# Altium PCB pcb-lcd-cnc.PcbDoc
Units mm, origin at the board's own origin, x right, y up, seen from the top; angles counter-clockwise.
Board outline 96.9 x 63.14 mm, 2 copper layers (Top Layer, Bottom Layer); 22 components, 40 nets, 120 pads, 47 vias.
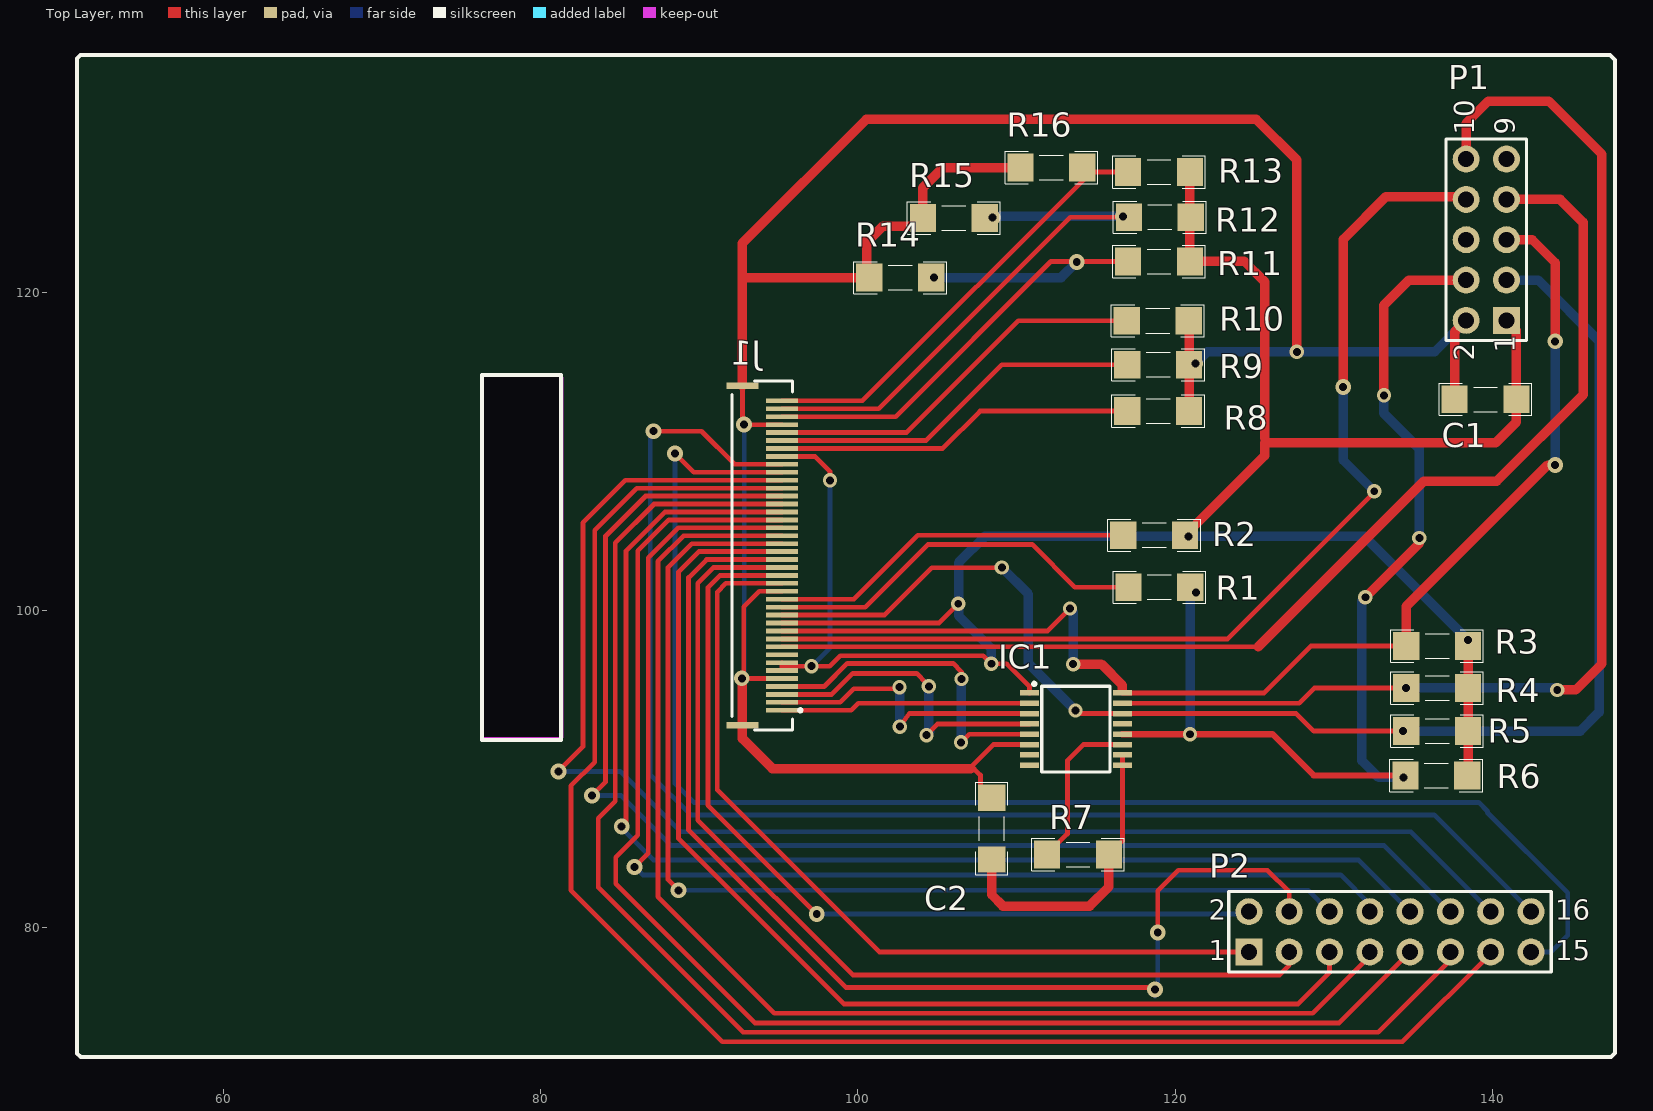
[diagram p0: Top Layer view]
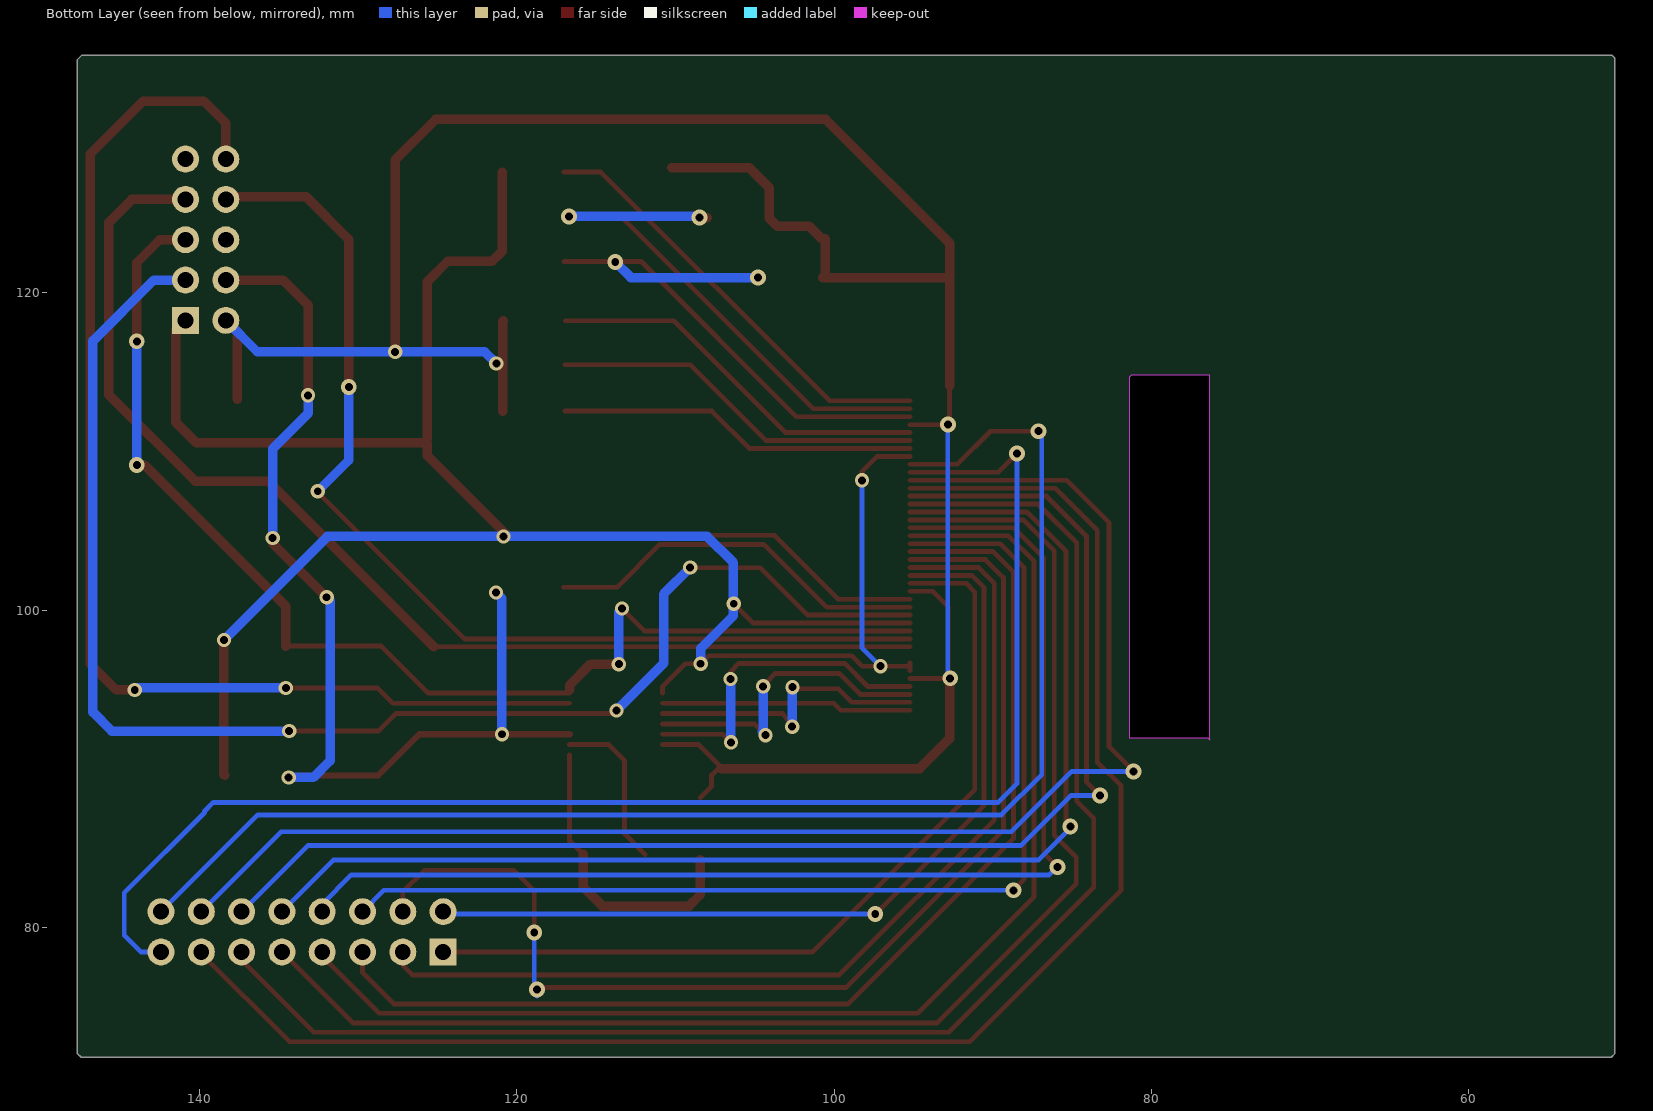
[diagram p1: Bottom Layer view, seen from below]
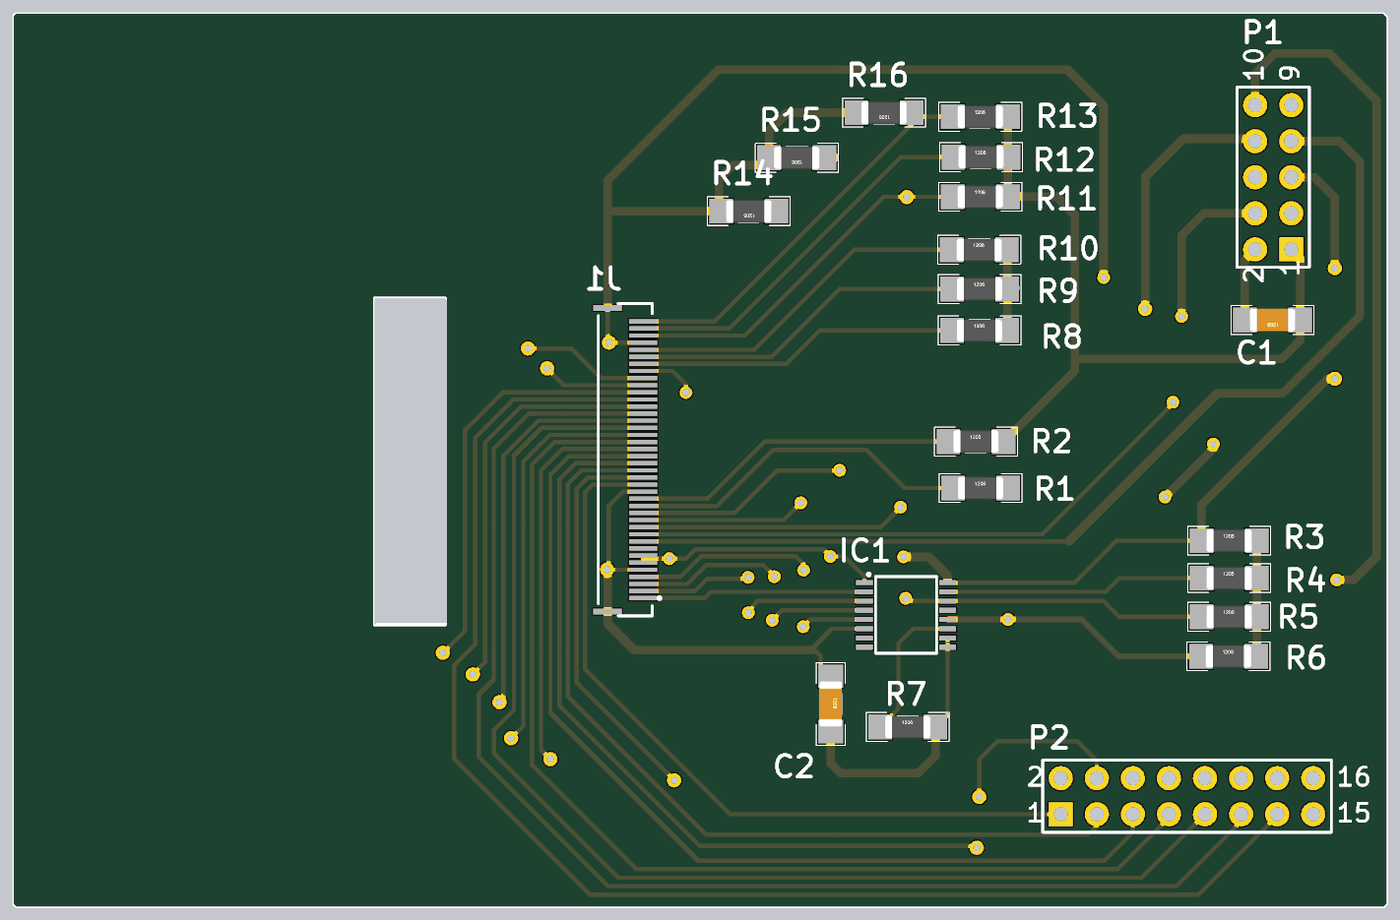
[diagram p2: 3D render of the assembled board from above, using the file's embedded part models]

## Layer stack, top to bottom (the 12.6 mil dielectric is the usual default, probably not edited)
Top Solder: solder mask 0.0102, Solder Resist, Dk 3.5
Top Layer: signal copper 0.0356
Dielectric 1: dielectric 0.32, FR-4, Dk 4.8
Bottom Layer: signal copper 0.0356
Bottom Solder: solder mask 0.0102, Solder Resist, Dk 3.5

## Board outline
51.029,71.831 50.8,72.06 50.8,134.772 51.003,134.976 147.396,134.976 147.701,134.671 147.701,72.085 147.447,71.831
cut-out: 76.327,114.808 81.28,114.808 81.407,114.681 81.407,91.948 76.454,91.948 76.327,91.821

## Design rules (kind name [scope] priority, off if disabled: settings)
Clearance [All] p1: gap=0.1 ignorepadtopadclearanceinfootprint=FALSE
PolygonConnect [All] p1: connectstyle=Relief reliefconductorwidth=0.254 reliefentries=4 polygonreliefangle="90 Angle" airgapwidth=0.254
RoutingVias [All] p1: holewidth=0.711 width=1.27 viastyle="Through Hole" minholewidth=0.711 minwidth=1.27 maxholewidth=0.711 maxwidth=1.27
SolderMaskExpansion [All] p1: expansion=0.102
Width [All] p1: maxlimit=0.6 minlimit=0.2 preferedwidth=0.3
30 further rules are at their usual default settings.

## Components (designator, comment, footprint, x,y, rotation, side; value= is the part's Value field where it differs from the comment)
C1 "0.1uF" CAPC4817X12N 139.548,113.284 r180 top
C2 "0.1uF" CAPC4817X12N 108.433,86.233 r270 top
IC1 "XPT2046" TSSOP16 113.741,92.507 r0 top
J1 "FFC2B28-40-G" GCT_FFC2B28-40-G 93.975,103.44 r90 top
P1 "Header 5X2" HDR2X5 140.868,118.262 r90 top
P2 "Header 8X2" HDR2X8 124.638,78.461 r0 top
R1 "1K" RESC4817X04N 118.999,101.448 r0 top
R2 "1K" RESC4817X04N 118.669,104.724 r0 top
R3 "1K" RESC4817X04N 136.5,97.739 r0 top
R4 "1K" RESC4817X04N 136.5,95.098 r0 top
R5 "1K" RESC4817X04N 136.5,92.38 r0 top
R6 "1K" RESC4817X04N 136.449,89.586 r0 top
R7 "1K" RESC4817X04N 113.868,84.607 r0 top
R8 "1K" RESC4817X04N 118.923,112.547 r0 top
R9 "1K" RESC4817X04N 118.923,115.468 r0 top
R10 "1K" RESC4817X04N 118.897,118.237 r0 top
R11 "1K" RESC4817X04N 118.974,121.971 r0 top
R12 "1K" RESC4817X04N 119.024,124.765 r0 top
R13 "1K" RESC4817X04N 118.974,127.61 r0 top
R14 "1K" RESC4817X04N 102.667,120.955 r180 top
R15 "1K" RESC4817X04N 106.045,124.714 r180 top
R16 "1K" RESC4817X04N 112.192,127.889 r180 top

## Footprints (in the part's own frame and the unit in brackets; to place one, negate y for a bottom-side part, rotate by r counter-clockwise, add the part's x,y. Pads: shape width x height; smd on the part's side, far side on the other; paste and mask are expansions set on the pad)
CAPC4817X12N [mm] "Chip Capacitor, 2-Leads, Body 4/80x1/70mm, IPC Medium Density-Design:Abbas Basereh"
  rect 1.65x1.75 smd: 1(-1.95,0) 2(1.95,0)
  silkscreen extent -2.92,-1.02 2.92,1.02, body extent -1.6,-0.8 1.6,0.8, height 1
GCT_FFC2B28-40-G [mm]
  rect 0.3x2 smd: 1(-9.75,-1.25) 2(-9.25,-1.25) 3(-8.75,-1.25) 4(-8.25,-1.25) 5(-7.75,-1.25) 6(-7.25,-1.25) 7(-6.75,-1.25) 8(-6.25,-1.25) 9(-5.75,-1.25) 10(-5.25,-1.25) 11(-4.75,-1.25) 12(-4.25,-1.25) 13(-3.75,-1.25) 14(-3.25,-1.25) 15(-2.75,-1.25) 16(-2.25,-1.25) 17(-1.75,-1.25) 18(-1.25,-1.25) 19(-0.75,-1.25) 20(-0.25,-1.25) 21(0.25,-1.25) 22(0.75,-1.25) 23(1.25,-1.25) 24(1.75,-1.25) 25(2.25,-1.25) 26(2.75,-1.25) 27(3.25,-1.25) 28(3.75,-1.25) 29(4.25,-1.25) 30(4.75,-1.25) 31(5.25,-1.25) 32(5.75,-1.25) 33(6.25,-1.25) 34(6.75,-1.25) 35(7.25,-1.25) 36(7.75,-1.25) 37(8.25,-1.25) 38(8.75,-1.25) 39(9.25,-1.25) 40(9.75,-1.25)
  rect 0.4x2 smd: S1(-10.7,1.25) S2(10.7,1.25)
  silkscreen extent -11,-2.5 11,1.9
HDR2X5 [mm] "Connector; Header; 5x2 Position"
  rect 1.7x1.7 hole 1: 1(0,0)
  round 1.7 hole 1: 2(0,2.54) 3(2.54,0) 4(2.54,2.54) 5(5.08,0) 6(5.08,2.54) 7(7.62,0) 8(7.62,2.54) 9(10.16,0) 10(10.16,2.54)
  silkscreen extent -1.27,-1.27 11.43,3.81
HDR2X8 [mm] "Connector; Header; 8x2 Position"
  rect 1.7x1.7 hole 1: 1(0,0)
  round 1.7 hole 1: 2(0,2.54) 3(2.54,0) 4(2.54,2.54) 5(5.08,0) 6(5.08,2.54) 7(7.62,0) 8(7.62,2.54) 9(10.16,0) 10(10.16,2.54) 11(12.7,0) 12(12.7,2.54) 13(15.24,0) 14(15.24,2.54) 15(17.78,0) 16(17.78,2.54)
  silkscreen extent -1.27,-1.27 19.05,3.81
RESC4817X04N [mm] "Chip Resistor, 2-Leads, Body 4/80x1/70mm, IPC Medium Density-Design:Abbas Basereh"
  rect 1.65x1.75 smd: 1(-1.95,0) 2(1.95,0)
  silkscreen extent -2.92,-1.02 2.92,1.02, body extent -1.6,-0.8 1.6,0.8, height 1
TSSOP16 [mm]
  rect 1.2x0.35 smd: 1(-2.925,2.275) 2(-2.925,1.625) 3(-2.925,0.975) 4(-2.925,0.325) 5(-2.925,-0.325) 6(-2.925,-0.975) 7(-2.925,-1.625) 8(-2.925,-2.275) 9(2.925,-2.275) 10(2.925,-1.625) 11(2.925,-0.975) 12(2.925,-0.325) 13(2.925,0.325) 14(2.925,0.975) 15(2.925,1.625) 16(2.925,2.275)
  silkscreen extent -2.72,-2.7 2.15,2.95

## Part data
C1 C2: library part "CAP SMD 1206", "CAP 1206"
IC1: "RASPBERRY PI 3.5 TFT DISPLAY", Package=Package
J1: "40 Position FFC, FPC Connector Contacts, Top and Bottom 0.020 _0.50mm_ Surface Mount, Right Angle", Package="Package Analog Devices"
P1: "Header, 5-Pin, Dual row"
P2: "Header, 8-Pin, Dual row"
R1 R2 R3 R4 R5 R6 R7 R8 R9 R10 R11 R12 R13 R14 R15 R16: library part "RES 1206 0.25W", "RES 1206"

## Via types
v1: diameter 0.9, hole 0.5, Top Layer to Bottom Layer, 28 vias
v2: diameter 1, hole 0.5, Top Layer to Bottom Layer, 19 vias

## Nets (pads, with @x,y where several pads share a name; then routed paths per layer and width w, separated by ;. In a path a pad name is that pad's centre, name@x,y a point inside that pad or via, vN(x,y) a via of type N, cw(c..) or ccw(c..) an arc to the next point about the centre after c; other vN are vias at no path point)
cs_lcd: J1.9 P1.7 | length 73.3
  Top Layer w0.3: J1.9 125.223,97.69
  Top Layer w0.6: 125.223,97.69 135.661,108.128 140.259,108.128 145.694,113.563 145.694,124.435 144.247,125.882 P1.7
cs_touch: IC1.15 P1.10 R4.1 | length 76.2
  Top Layer w0.3: IC1.15 127.812,94.132 128.778,95.098 v1(134.55,95.098)
  Top Layer w0.6: P1.10 138.328,130.683 139.725,132.08 143.535,132.08 146.888,128.727 146.888,96.622 145.237,94.971 v1(144.069,94.971)
  Bottom Layer w0.6: v1(134.55,95.098) v1@144.069,95.098
d0: J1.17 P2.1 | length 54.5
  Top Layer w0.3: J1.17 91.682,101.69 91.135,101.143 91.135,88.671 101.346,78.461 P2.1
d1: J1.18 P2.2 | length 55.7
  Top Layer w0.3: J1.18 91.319,102.19 90.551,101.422 90.551,87.706 v2(97.409,80.848)
  Bottom Layer w0.3: v2(97.409,80.848) 124.485,80.848 P2.2
d2: J1.19 P2.3 | length 63
  Top Layer w0.3: J1.19 90.904,102.69 89.916,101.702 89.916,86.766 99.67,77.013 126.568,77.013 127.178,77.622 P2.3
d3: J1.20 P2.4 | length 73.5
  Top Layer w0.3: J1.20 90.464,103.19 89.332,102.057 89.332,86.131 99.238,76.225 118.313,76.225 v2@118.618,75.921 ; v2(118.897,79.68) 118.897,82.321 120.193,83.617 125.806,83.617 127.178,82.245 P2.4
  Bottom Layer w0.3: v2(118.72,76.098) 118.72,75.692 118.897,75.87 v2(118.897,79.68)
d4: J1.21 P2.5 | length 71.3
  Top Layer w0.3: J1.21 89.974,103.69 88.697,102.413 88.697,85.598 99.111,75.184 127.737,75.184 129.718,77.165 P2.5
d5: J1.22 P2.6 | length 70
  Top Layer w0.3: v2(88.697,82.347) 88.036,83.007 88.036,102.692 89.534,104.19 J1.22
  Bottom Layer w0.3: v2(88.697,82.347) 128.372,82.347 P2.6
d6: J1.23 P2.7 | length 79.3
  Top Layer w0.3: J1.23 89.018,104.69 87.401,103.073 87.401,81.94 94.742,74.6 128.651,74.6 132.258,78.207 P2.7
d7: J1.24 P2.8 | length 76.7
  Top Layer w0.3: v2@86.042,83.934 86.792,84.684 86.792,103.302 88.68,105.19 J1.24
  Bottom Layer w0.3: v2(85.928,83.82) 86.436,83.312 130.429,83.312 132.258,81.483 P2.8
d8: J1.25 P2.9 | length 87
  Top Layer w0.3: J1.25 88.088,105.69 86.131,103.734 86.131,85.827 84.734,84.43 84.734,82.753 93.497,73.99 130.327,73.99 P2.9
d9: J1.26 P2.10 | length 80.1
  Top Layer w0.3: v2(85.115,86.36) 85.395,86.639 85.395,103.734 87.851,106.19 J1.26
  Bottom Layer w0.3: v2@84.938,86.36 v2(85.115,86.36) ; v2@85.344,86.03 87.122,84.252 131.547,84.252 P2.10
d10: J1.27 P2.11 | length 93.6
  Top Layer w0.3: J1.27 87.157,106.69 84.709,104.242 84.709,87.96 83.642,86.893 83.642,82.525 92.761,73.406 132.791,73.406 137.338,77.953 P2.11
d11: J1.28 P2.12 | length 86
  Top Layer w0.3: v2(83.236,88.316) 84.099,89.179 84.099,104.673 86.616,107.19 J1.28
  Bottom Layer w0.3: v2(83.236,88.316) 85.09,88.316 88.24,85.166 133.172,85.166 P2.12
d12: J1.29 P2.13 | length 100.5
  Top Layer w0.3: J1.29 86.074,107.69 83.414,105.029 83.414,90.424 81.915,88.925 81.915,82.347 91.465,72.796 134.315,72.796 139.878,78.359 P2.13
d13: J1.30 P2.14 | length 92.4
  Top Layer w0.3: v2(81.128,89.84) 82.677,91.389 82.677,105.512 85.355,108.19 J1.30
  Bottom Layer w0.3: v2(81.128,89.84) 85.014,89.84 88.824,86.03 134.849,86.03 P2.14
d14: J1.31 P2.15 | length 92.6
  Top Layer w0.3: v2(88.468,109.88) 89.659,108.69 J1.31
  Bottom Layer w0.3: v2(88.468,109.88) 88.468,89.078 89.662,87.884 139.116,87.884 139.675,87.325 139.675,87.249 144.729,82.194 144.729,79.502 143.688,78.461 P2.15
d15: J1.32 P2.16 | length 89.8
  Top Layer w0.3: v2(87.122,111.277) 90.145,111.277 92.232,109.19 J1.32
  Bottom Layer w0.3: v2@86.919,111.277 86.919,89.637 89.459,87.097 136.322,87.097 P2.16 ; v2@87.071,111.328 v2(87.122,111.277)
GND: C1.2 C2.1 IC1.6 J1.5 J1.16 J1.37 J1.S1 J1.S2 P1.2 R8.2 R9.2 R10.2 R14.2 R15.2 R16.2 | length 169.4
  Top Layer w0.3: v2@92.725,95.707 92.812,95.794 92.812,100.203 93.798,101.19 J1.16 ; J1.S2 92.725,111.797 v2(92.832,111.69) J1.37 ; v2@92.767,95.69 J1.5 ; C2.1 107.721,88.894 107.721,89.611 107.315,90.018 107.01,90.018 108.524,91.532 IC1.6
  Top Layer w0.6: v2@92.725,95.707 J1.S1 92.725,91.908 94.615,90.018 107.112,90.018 ; J1.S2 92.725,120.955 ; R16.2 105.359,127.889 104.095,126.625 R15.2 103.587,124.206 101.575,124.206 100.762,123.393 100.559,123.393 100.559,121.113 R14.2 92.725,120.955 ; R10.2 120.873,118.212 R9.2@120.873,115.545 ; R8.2 R9.2 ; v1(127.66,116.281) 127.66,128.372 125.095,130.937 100.533,130.937 92.725,123.128 92.725,120.955 ; C1.2 137.598,117.532 P1.2
  Bottom Layer w0.3: v2(92.685,95.707) 92.634,95.707 92.832,95.906 v2(92.832,111.69)
  Bottom Layer w0.6: v1(121.285,115.545) 122.022,116.281 v1(127.66,116.281) 136.347,116.281 P1.2
miso: IC1.12 P1.4 R1.2 R6.1 | length 68.2
  Top Layer w0.3: v1(134.372,89.459) R6.1
  Top Layer w0.4: IC1.12 v1(120.929,92.182) 126.131,92.182 128.727,89.586 R6.1
  Top Layer w0.6: v1(131.978,100.813) 135.382,104.216 v1(135.382,104.546) ; v1(133.147,113.538) 133.147,119.228 134.722,120.802 P1.4
  Bottom Layer w0.6: v1(120.929,92.182) 120.929,100.736 v1(121.31,101.117) ; v1(131.978,100.813) 131.75,100.584 131.75,90.526 132.817,89.459 v1(134.372,89.459) ; v1(133.147,113.538) 133.147,112.395 135.382,110.16 v1(135.382,104.546)
mosi: IC1.14 J1.13 P1.3 R5.1 | length 91
  Top Layer w0.3: J1.13 101.671,99.69 104.648,102.667 v1@109.017,102.667 ; v1(113.716,93.675) 113.909,93.482 IC1.14 127.625,93.482 128.727,92.38 v1(134.341,92.38) R5.1
  Bottom Layer w0.6: v1(109.068,102.692) 110.744,101.016 110.744,96.647 v1(113.716,93.675) ; v1(134.341,92.38) 145.517,92.38 146.71,93.574 146.71,116.967 142.875,120.802 P1.3
NetC2_2: C2.2 IC1.9 IC1.10 R7.2 | length 19.1
  Top Layer w0.3: R7.2 116.666,85.455 IC1.9 IC1.10
  Top Layer w0.6: C2.2 108.433,82.067 109.144,81.356 114.605,81.356 115.818,82.57 R7.2
NetIC1_11: IC1.11 R7.1 | length 10.3
  Top Layer w0.3: R7.1 113.208,85.897 113.208,90.526 114.214,91.532 IC1.11
NetJ1_14: J1.14 R1.1 | length 24.6
  Top Layer w0.3: J1.14 100.469,100.19 104.419,104.14 110.973,104.14 113.665,101.448 R1.1
NetJ1_15: J1.15 R2.1 | length 23.2
  Top Layer w0.3: J1.15 99.75,100.69 103.784,104.724 R2.1
NetJ1_34: J1.34 R8.1 | length 22.7
  Top Layer w0.3: J1.34 105.338,110.19 107.696,112.547 R8.1
NetJ1_35: J1.35 R9.1 | length 23.7
  Top Layer w0.3: J1.35 104.289,110.69 109.068,115.468 R9.1
NetJ1_36: J1.36 R10.1 | length 24.6
  Top Layer w0.3: J1.36 103.062,111.19 110.109,118.237 R10.1
NetJ1_38: J1.38 R11.1 R14.1 | length 35.4
  Top Layer w0.3: J1.38 102.385,112.19 112.166,121.971 R11.1
  Top Layer w0.6: R14.1 v2(104.8,120.955)
  Bottom Layer w0.6: v2(104.8,120.955) 112.801,120.955 v2(113.792,121.945)
NetJ1_39: J1.39 R12.1 R15.1 | length 35.3
  Top Layer w0.3: J1.39 101.311,112.69 113.386,124.765 R12.1@116.713,124.765
  Top Layer w0.6: R15.1 108.458,124.714 v2(108.483,124.739)
  Bottom Layer w0.6: v2(108.483,124.739) 108.56,124.816 v2(116.713,124.816)
NetJ1_40: J1.40 R13.1 R16.1 | length 27.8
  Top Layer w0.3: J1.40 100.287,113.19 114.706,127.61 R13.1
NetLabel103: P1.6
NetLabel108: P1.9
rs: J1.10 P1.8 | length 66.9
  Top Layer w0.2: v1(132.537,107.493) v1@132.613,107.493
  Top Layer w0.3: J1.10 123.31,98.19 v1@132.613,107.493 ; P1.8@138.151,126.06 P1.8
  Top Layer w0.6: v2(130.581,114.071) 130.581,123.368 133.274,126.06 P1.8@138.151,126.06
  Bottom Layer w0.6: v2(130.581,114.071) 130.581,109.449 v1(132.537,107.493)
sck: IC1.16 J1.11 P1.5 R3.1 | length 77.6
  Top Layer w0.2: IC1.16 116.666,94.971
  Top Layer w0.3: J1.11 111.949,98.69 v1(113.36,100.101) ; IC1.16 125.592,94.782 128.549,97.739 R3.1
  Top Layer w0.6: v1(113.563,96.596) 115.341,96.596 116.666,95.271 116.666,94.971 ; R3.1 134.55,100.234 143.459,109.144 v2(143.942,109.144) ; P1.5 142.494,123.342 143.942,121.895 v2(143.942,116.942)
  Bottom Layer w0.6: v1(113.36,100.101) 113.563,99.898 v1(113.563,96.596) ; v2(143.942,109.144) v2(143.942,116.942)
VCC: C1.1 IC1.1 J1.6 J1.7 J1.12 J1.33 P1.1 R2.2 R3.2 R4.2 R5.2 R6.2 R11.2 R12.2 R13.2 | length 147.9
  Top Layer w0.3: J1.6 95.225,96.469 ; J1.7 95.225,96.469 ; J1.12 105.108,99.19 v1(106.324,100.406) ; J1.33 97.295,109.69 98.247,108.737 v1(98.247,108.179) ; IC1.1 110.816,95.178 109.372,96.622 v1(108.407,96.622) 107.899,97.13 98.882,97.13 98.222,96.469 v1(97.079,96.469) 95.225,96.469
  Top Layer w0.6: R2.2 125.628,109.734 125.628,110.541 140.183,110.541 141.498,111.856 C1.1 141.498,117.633 P1.1 ; R13.2 120.924,122.612 121.552,121.983 124.346,121.983 125.628,120.701 125.628,110.846 ; R6.2 138.45,89.637 R5.2 R4.2 R3.2 v1(138.45,98.126)
  Bottom Layer w0.3: v1(97.079,96.469) 98.247,97.638 v1(98.247,108.179)
  Bottom Layer w0.6: v1(106.324,100.406) 106.35,100.381 106.35,99.644 108.407,97.587 v1(108.407,96.622) ; v1@106.35,100.406 106.35,102.997 108.001,104.648 v1(120.828,104.648) 131.928,104.648 v1(138.45,98.126)
x+: IC1.2 J1.1 | length 15.8
  Top Layer w0.3: J1.1 99.583,93.69 100.025,94.132 IC1.2
x-: IC1.4 J1.3 | length 19.9
  Top Layer w0.3: J1.3 98.347,94.69 99.67,96.012 103.708,96.012 v1@104.318,95.402 ; v1(104.318,92.126) 105.024,92.832 IC1.4
  Bottom Layer w0.6: v1(104.318,92.126) 104.521,92.329 104.47,92.38 v1(104.47,95.199)
y+: IC1.3 J1.2 | length 18.9
  Top Layer w0.3: J1.2 98.889,94.19 99.746,95.047 102.387,95.047 102.286,95.148 v1(102.616,95.148) ; v1(102.641,92.659) 103.235,93.482 IC1.3
  Bottom Layer w0.6: v1(102.641,92.659) v1@102.641,95.021
y-: IC1.5 J1.4 | length 21.4
  Top Layer w0.3: J1.4 97.882,95.19 99.339,96.647 105.994,96.647 106.528,96.114 v1(106.528,95.656) ; v1(106.502,91.669) 107.015,92.182 IC1.5
  Bottom Layer w0.6: v1(106.502,91.669) 106.502,95.783 106.528,95.758 v1(106.528,95.656)
pads on no net: IC1.7 IC1.8 IC1.13 J1.8

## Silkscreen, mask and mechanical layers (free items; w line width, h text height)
Top Overlay:
  lines w0.254: 50.8,72.06 50.8,134.772 51.003,134.976 147.396,134.976 147.701,134.671 147.701,72.085 147.447,71.831 51.029,71.831 50.8,72.06 ; 76.327,91.821 76.327,114.808 81.28,114.808 81.28,91.821 76.327,91.821
Mechanical 2:
  lines w0.013: 51.749,72.358 51.749,134.358 146.749,134.358 146.749,72.358 51.749,72.358 ; 76.365,91.834 76.365,114.834 81.365,114.834 81.365,91.834 76.365,91.834 ; 91.634,92.058 91.634,115.058 96.634,115.058 96.634,92.058 91.634,92.058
